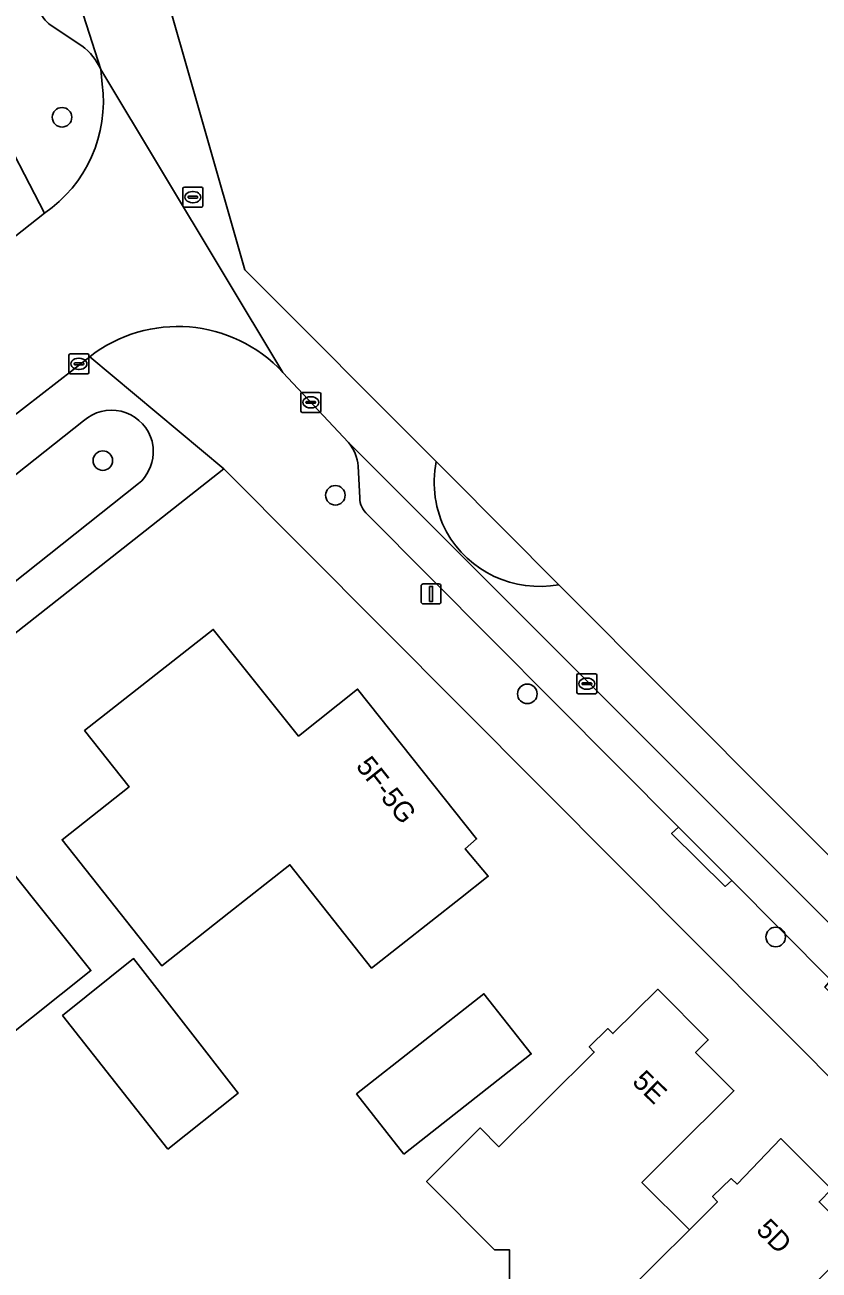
# Model space of a CAD drawing. Extents: x 159499 to 160349, y 382524 to 383273.
# Drawn here: x 160006.4 to 160046.1, y 383112.7 to 383174.9 of the extents above; entities that cross this region are included whole.
import ezdxf

# ---------------------------------------------------------------- set-up
doc = ezdxf.new("R2010")
doc.units = 0
for name, color, linetype in [('IMGEO_Boom', 7, 'Continuous'), ('IMGEO_Erf', 7, 'Continuous'), ('IMGEO_Groenvoorziening', 7, 'Continuous'), ('IMGEO_Kolk', 7, 'Continuous'), ('IMGEO_Lichtmast', 7, 'Continuous'), ('IMGEO_Pand', 7, 'Continuous'), ('IMGEO_Pand_nummerreeks', 7, 'Continuous'), ('IMGEO_Parkeervlak_open', 7, 'Continuous'), ('IMGEO_Rijbaan_lokaal_open', 7, 'Continuous'), ('IMGEO_Rioolput', 7, 'Continuous'), ('IMGEO_Voetpad_open', 7, 'Continuous')]:
    doc.layers.add(name, color=color, linetype=linetype)

msp = doc.modelspace()

# ---------------------------------------------------------------- linework, layer by layer
at = {"layer": 'IMGEO_Boom'}
for centre in [(160008.214, 383170.317), (160010.256, 383153.147), (160021.884, 383151.415), (160031.484, 383141.482), (160043.906, 383129.323)]:
    msp.add_circle(centre, 0.489, dxfattribs=at)
at = {"layer": 'IMGEO_Erf'}
for points in [[(160069.07, 383073.156), (160071.919, 383076.914), (160077.006, 383081.993), (160081.991, 383086.829), (160067.75, 383101.08), (160016.301, 383152.744), (160001.274, 383140.9), (160002.826, 383138.938), (160000, 383136.696), (159969.339, 383112.369), (160000, 383073.962), (160006.879, 383065.344), (160051.214, 383033.728), (160053.92, 383031.798), (160060.452, 383040.944)], [(160030.58, 383110.504), (160030.598, 383113.675), (160029.836, 383113.679), (160026.442, 383117.102), (160029.132, 383119.771), (160030.062, 383118.834), (160034.833, 383123.565), (160034.577, 383123.828), (160035.504, 383124.744), (160035.763, 383124.493), (160038.003, 383126.714), (160040.531, 383124.177), (160039.901, 383123.546), (160041.817, 383121.634), (160038.641, 383118.472), (160037.215, 383117.052), (160039.586, 383114.674), (160040.99, 383116.079), (160040.749, 383116.34), (160041.669, 383117.242), (160041.984, 383116.966), (160044.168, 383119.245), (160046.692, 383116.707)]]:
    msp.add_lwpolyline(points, dxfattribs=at)
for points in [[(160016.558, 383130.525), (160013.211, 383127.876), (160008.217, 383134.186), (160011.565, 383136.836), (160009.341, 383139.648), (160015.779, 383144.707), (160020.043, 383139.37), (160022.992, 383141.72), (160028.948, 383134.232), (160028.37, 383133.728), (160029.529, 383132.362), (160028.136, 383131.264), (160023.699, 383127.767), (160019.608, 383132.939)], [(160004.209, 383119.058), (160002.296, 383117.538), (160002.349, 383117.471), (160000, 383115.631), (159996.451, 383112.851), (159994.2, 383115.629), (159990.696, 383112.874), (159987.999, 383116.264), (159984.887, 383120.176), (159990.894, 383124.991), (159992.99, 383122.344), (159994.232, 383120.776), (159997.365, 383123.295), (159996.151, 383124.828), (159996.416, 383125.034), (159998.829, 383121.957), (160000.398, 383123.188), (160000, 383123.688), (159995.843, 383128.911), (160000, 383132.215), (160003.671, 383135.132), (160006.794, 383131.227), (160009.659, 383127.643), (160002.137, 383121.666)], [(160013.507, 383118.714), (160008.245, 383125.389), (160011.792, 383128.245), (160017.019, 383121.506)], [(160025.306, 383118.47), (160022.943, 383121.478), (160029.314, 383126.485), (160031.676, 383123.476)]]:
    msp.add_lwpolyline(points, close=True, dxfattribs=at)
at = {"layer": 'IMGEO_Groenvoorziening'}
for points in [[(160009.287, 383155.131), (160000, 383147.78), (159987.796, 383138.118), (159990.398, 383134.835), (160000, 383142.448), (160012.044, 383151.997)], [(160012.775, 383153.48), (160012.772, 383153.8), (160012.72, 383154.114), (160012.639, 383154.337)]]:
    msp.add_lwpolyline(points, dxfattribs=at)
for centre, radius, start, end in [((160010.691, 383153.585), 2.088, 21.1107, 132.23683), ((160010.695, 383153.584), 2.083, 310.37848, 357.14233)]:
    msp.add_arc(centre, radius, start, end, dxfattribs=at)
at = {"layer": 'IMGEO_Kolk'}
for p, q in [((160008.56, 383157.561), (160008.56, 383158.413)), ((160008.635, 383158.487), (160009.487, 383158.487)), ((160008.819, 383157.981), (160008.819, 383157.993)), ((160009.257, 383157.944), (160008.859, 383157.944)), ((160008.862, 383158.03), (160009.26, 383158.03)), ((160009.048, 383158.267), (160009.073, 383158.267)), ((160009.303, 383157.993), (160009.303, 383157.981)), ((160009.561, 383158.413), (160009.561, 383157.561)), ((160009.487, 383157.487), (160008.635, 383157.487)), ((160009.071, 383157.707), (160009.046, 383157.707)), ((160020.154, 383155.635), (160020.154, 383156.487)), ((160020.229, 383156.561), (160021.081, 383156.561)), ((160020.413, 383156.055), (160020.413, 383156.067)), ((160020.456, 383156.104), (160020.854, 383156.104)), ((160020.642, 383156.341), (160020.667, 383156.341)), ((160020.897, 383156.067), (160020.897, 383156.055)), ((160021.155, 383156.487), (160021.155, 383155.635)), ((160021.081, 383155.561), (160020.229, 383155.561)), ((160020.851, 383156.018), (160020.453, 383156.018)), ((160020.665, 383155.781), (160020.64, 383155.781)), ((160033.959, 383141.564), (160033.959, 383142.416)), ((160034.034, 383142.49), (160034.886, 383142.49)), ((160034.96, 383142.416), (160034.96, 383141.564)), ((160034.218, 383141.984), (160034.218, 383141.996)), ((160034.656, 383141.947), (160034.258, 383141.947)), ((160034.261, 383142.033), (160034.659, 383142.033)), ((160034.447, 383142.27), (160034.472, 383142.27)), ((160034.702, 383141.996), (160034.702, 383141.984)), ((160034.886, 383141.49), (160034.034, 383141.49)), ((160034.47, 383141.71), (160034.445, 383141.71))]:
    msp.add_line(p, q, dxfattribs=at)
for points in [[(160008.56, 383157.561), (160008.56, 383158.413)], [(160008.635, 383158.487), (160009.487, 383158.487)], [(160009.561, 383158.413), (160009.561, 383157.561)], [(160009.487, 383157.487), (160008.635, 383157.487)], [(160020.154, 383155.635), (160020.154, 383156.487)], [(160020.229, 383156.561), (160021.081, 383156.561)], [(160021.155, 383156.487), (160021.155, 383155.635)], [(160021.081, 383155.561), (160020.229, 383155.561)], [(160033.959, 383141.564), (160033.959, 383142.416)], [(160034.034, 383142.49), (160034.886, 383142.49)], [(160034.96, 383142.416), (160034.96, 383141.564)], [(160034.886, 383141.49), (160034.034, 383141.49)]]:
    msp.add_lwpolyline(points, dxfattribs=at)
for centre, radius, start, end in [((160008.637, 383158.411), 0.0765, 91.55205, 178.44795), ((160008.637, 383158.411), 0.0765, 91.55205, 178.44795), ((160008.859, 383157.99), 0.0403, 85.87752, 175.75265), ((160008.856, 383157.98), 0.0366, 178.93798, 274.71019), ((160009.26, 383157.987), 0.043, 264.86636, 352.45326), ((160009.264, 383157.992), 0.0386, 1.73085, 96.63898), ((160009.485, 383158.411), 0.0765, 1.55205, 88.44795), ((160009.485, 383158.411), 0.0765, 1.55205, 88.44795), ((160008.637, 383157.563), 0.0765, 181.55205, 268.44795), ((160008.637, 383157.563), 0.0765, 181.55205, 268.44795), ((160009.485, 383157.563), 0.0765, 271.55205, 358.44795), ((160009.485, 383157.563), 0.0765, 271.55205, 358.44795), ((160020.231, 383156.485), 0.0765, 91.55205, 178.44795), ((160020.231, 383156.485), 0.0765, 91.55205, 178.44795), ((160020.453, 383156.064), 0.0403, 85.87752, 175.75265), ((160020.45, 383156.054), 0.0366, 178.93798, 274.71019), ((160020.854, 383156.061), 0.043, 264.86636, 352.45326), ((160020.858, 383156.066), 0.0386, 1.73085, 96.63898), ((160021.079, 383156.485), 0.0765, 1.55205, 88.44795), ((160021.079, 383156.485), 0.0765, 1.55205, 88.44795), ((160020.231, 383155.637), 0.0765, 181.55205, 268.44795), ((160020.231, 383155.637), 0.0765, 181.55205, 268.44795), ((160021.079, 383155.637), 0.0765, 271.55205, 358.44795), ((160021.079, 383155.637), 0.0765, 271.55205, 358.44795), ((160034.036, 383142.414), 0.0765, 91.55205, 178.44795), ((160034.036, 383142.414), 0.0765, 91.55205, 178.44795), ((160034.884, 383142.414), 0.0765, 1.55205, 88.44795), ((160034.884, 383142.414), 0.0765, 1.55205, 88.44795), ((160034.258, 383141.993), 0.0403, 85.87752, 175.75265), ((160034.255, 383141.983), 0.0366, 178.93798, 274.71019), ((160034.659, 383141.99), 0.043, 264.86636, 352.45326), ((160034.663, 383141.995), 0.0386, 1.73085, 96.63898), ((160034.036, 383141.566), 0.0765, 181.55205, 268.44795), ((160034.036, 383141.566), 0.0765, 181.55205, 268.44795), ((160034.884, 383141.566), 0.0765, 271.55205, 358.44795), ((160034.884, 383141.566), 0.0765, 271.55205, 358.44795)]:
    msp.add_arc(centre, radius, start, end, dxfattribs=at)
for centre, major_axis, ratio, start_param, end_param in [((160009.047, 383157.987), (-0.387, 0.002), 0.722429, 4.712389, 7.853982), ((160009.072, 383157.987), (-0.39, 0.002), 0.717154, 1.570796, 4.712389), ((160020.641, 383156.061), (-0.387, 0.002), 0.722429, 4.712389, 7.853982), ((160020.666, 383156.061), (-0.39, 0.002), 0.717154, 1.570796, 4.712389), ((160034.446, 383141.99), (-0.387, 0.002), 0.722429, 4.712389, 7.853982), ((160034.471, 383141.99), (-0.39, 0.002), 0.717154, 1.570796, 4.712389)]:
    msp.add_ellipse(centre, major_axis=major_axis, ratio=ratio, start_param=start_param, end_param=end_param, dxfattribs=at)
at = {"layer": 'IMGEO_Lichtmast'}
for p, q in [((160026.174, 383146.083), (160026.174, 383146.883)), ((160026.174, 383146.883), (160026.174, 383146.083)), ((160026.274, 383146.983), (160027.064, 383146.983)), ((160027.064, 383146.983), (160026.274, 383146.983)), ((160027.164, 383146.883), (160027.164, 383146.083)), ((160027.164, 383146.083), (160027.164, 383146.883)), ((160027.064, 383145.983), (160026.274, 383145.983)), ((160026.274, 383145.983), (160027.064, 383145.983))]:
    msp.add_line(p, q, dxfattribs=at)
msp.add_lwpolyline([(160026.594, 383146.858), (160026.744, 383146.858), (160026.744, 383146.108), (160026.594, 383146.108), (160026.594, 383146.858)], dxfattribs=at)
for centre, start, end in [((160026.274, 383146.883), 90, 180), ((160026.274, 383146.883), 90, 180), ((160027.064, 383146.883), 0, 90), ((160027.064, 383146.883), 360, 90), ((160026.274, 383146.083), 180, 270), ((160026.274, 383146.083), 180, 270), ((160027.064, 383146.083), 270, 0), ((160027.064, 383146.083), 270, 0)]:
    msp.add_arc(centre, 0.1, start, end, dxfattribs=at)
at = {"layer": 'IMGEO_Pand'}
for points in [[(160022.992, 383141.72), (160020.043, 383139.37), (160015.779, 383144.707), (160009.341, 383139.648), (160011.565, 383136.836), (160008.217, 383134.186), (160013.211, 383127.876), (160016.558, 383130.525), (160019.608, 383132.939), (160023.699, 383127.767), (160028.136, 383131.264), (160029.529, 383132.362), (160028.37, 383133.728), (160028.948, 383134.232)], [(160006.794, 383131.227), (160003.671, 383135.132), (160000, 383132.215), (159995.843, 383128.911), (160000, 383123.688), (160000.398, 383123.188), (159998.829, 383121.957), (159999.502, 383121.1), (160000, 383120.466), (160002.296, 383117.538), (160004.209, 383119.058), (160002.137, 383121.666), (160009.659, 383127.643)], [(160013.507, 383118.714), (160017.019, 383121.506), (160011.792, 383128.245), (160008.245, 383125.389)], [(160025.306, 383118.47), (160031.676, 383123.476), (160029.314, 383126.485), (160022.943, 383121.478)], [(160036.311, 383111.257), (160036.228, 383111.34), (160039.586, 383114.674), (160037.215, 383117.052), (160038.641, 383118.472), (160041.817, 383121.634), (160039.901, 383123.546), (160040.531, 383124.177), (160038.003, 383126.714), (160035.763, 383124.493), (160035.504, 383124.744), (160034.577, 383123.828), (160034.833, 383123.565), (160030.062, 383118.834), (160029.132, 383119.771), (160026.442, 383117.102), (160029.836, 383113.679), (160030.598, 383113.675), (160030.58, 383110.504), (160032.964, 383108.099), (160033.044, 383108.018)], [(160047.989, 383114.149), (160046.077, 383116.072), (160046.692, 383116.707), (160044.168, 383119.245), (160041.984, 383116.966), (160041.669, 383117.242), (160040.749, 383116.34), (160040.99, 383116.079), (160039.586, 383114.674), (160036.228, 383111.34), (160036.311, 383111.257), (160038.846, 383108.701), (160036.851, 383106.723), (160036.843, 383102.926), (160039.147, 383100.602), (160042.399, 383103.856), (160045.76, 383107.219), (160043.439, 383109.554)]]:
    msp.add_lwpolyline(points, close=True, dxfattribs=at)
at = {"layer": 'IMGEO_Parkeervlak_open'}
for points in [[(160010.148, 383172.703), (160009.286, 383175.416), (160008.427, 383178.634), (160001.127, 383207.052)], [(160007.624, 383174.938), (160009.21, 383173.884)], [(160076.557, 383100.013), (160076.086, 383100.485), (160022.535, 383154.053)], [(160023.019, 383152.872), (160023.102, 383151.29)], [(160023.491, 383150.457), (160039.036, 383134.817), (160041.708, 383132.149), (160046.658, 383127.167), (160049.325, 383124.473), (160053.562, 383120.199), (160056.249, 383117.477), (160059.79, 383113.973), (160066.209, 383107.501), (160070.134, 383103.56), (160072.795, 383100.861)]]:
    msp.add_lwpolyline(points, dxfattribs=at)
for centre, radius, start, end in [((160008.417, 383176.075), 1.386, 197.12192, 235.11954), ((160007.643, 383171.676), 2.707, 22.28585, 54.63032), ((160020.952, 383152.714), 2.073, 4.35881, 40.211), ((160024.232, 383151.31), 1.13, 181.02247, 229.04143)]:
    msp.add_arc(centre, radius, start, end, dxfattribs=at)
at = {"layer": 'IMGEO_Rijbaan_lokaal_open'}
for points in [[(160026.926, 383153.096), (160017.356, 383162.697), (160004.31, 383208.29), (160003.465, 383211.242), (159997.514, 383226.3), (159968.231, 383262.808), (159963.898, 383259.136), (159970.978, 383250.787), (159972.768, 383248.666), (159984.285, 383235.173), (159987.671, 383231.155), (159988.81, 383229.825), (159991.015, 383227.22), (159992.828, 383224.63), (159995.219, 383220.768), (159995.36, 383220.508), (159997.004, 383217.494)], [(160001.127, 383207.052), (160008.427, 383178.634), (160009.286, 383175.416), (160010.148, 383172.703), (160019.26, 383157.562), (160022.535, 383154.053), (160076.086, 383100.485), (160077.721, 383102.136)], [(160019.26, 383157.562), (160010.148, 383172.703), (160010.226, 383171.982)], [(160007.337, 383165.518), (159985.41, 383148.209), (159982.548, 383145.937), (159982.197, 383145.658), (159979.79, 383143.748), (159968.366, 383134.687), (159965.633, 383132.52), (159965.323, 383132.274), (159962.64, 383130.146), (159961.424, 383129.181), (159965.635, 383123.738), (160005.521, 383155.177), (160009.599, 383158.345)], [(160033.061, 383146.941), (160027.541, 383152.479), (160026.926, 383153.096)], [(160077.721, 383102.136), (160033.061, 383146.941)]]:
    msp.add_lwpolyline(points, dxfattribs=at)
for centre, radius, start, end in [((160003.506, 383171.108), 6.776, 304.42366, 7.41309), ((160014.002, 383152.682), 7.173, 42.86559, 127.8673), ((160032.169, 383152.066), 5.343, 168.88651, 207.71092), ((160032.169, 383152.066), 5.343, 168.88651, 207.71092), ((160032.093, 383152.187), 5.334, 209.24423, 280.45081), ((160032.093, 383152.187), 5.334, 209.24423, 280.45081)]:
    msp.add_arc(centre, radius, start, end, dxfattribs=at)
at = {"layer": 'IMGEO_Rioolput'}
for p, q in [((160014.257, 383165.898), (160014.257, 383166.75)), ((160014.332, 383166.824), (160015.184, 383166.824)), ((160015.258, 383166.75), (160015.258, 383165.898)), ((160014.516, 383166.318), (160014.516, 383166.33)), ((160014.954, 383166.281), (160014.556, 383166.281)), ((160014.559, 383166.367), (160014.957, 383166.367)), ((160014.768, 383166.044), (160014.743, 383166.044)), ((160014.745, 383166.604), (160014.77, 383166.604)), ((160015, 383166.33), (160015, 383166.318)), ((160015.184, 383165.824), (160014.332, 383165.824))]:
    msp.add_line(p, q, dxfattribs=at)
for points in [[(160014.257, 383165.898), (160014.257, 383166.75)], [(160014.332, 383166.824), (160015.184, 383166.824)], [(160015.258, 383166.75), (160015.258, 383165.898)], [(160015.184, 383165.824), (160014.332, 383165.824)]]:
    msp.add_lwpolyline(points, dxfattribs=at)
for centre, radius, start, end in [((160014.334, 383166.748), 0.0765, 91.55205, 178.44795), ((160014.334, 383166.748), 0.0765, 91.55205, 178.44795), ((160015.182, 383166.748), 0.0765, 1.55205, 88.44795), ((160015.182, 383166.748), 0.0765, 1.55205, 88.44795), ((160014.556, 383166.327), 0.0403, 85.87752, 175.75265), ((160014.553, 383166.317), 0.0366, 178.93798, 274.71019), ((160014.957, 383166.324), 0.043, 264.86636, 352.45326), ((160014.961, 383166.329), 0.0386, 1.73085, 96.63898), ((160014.334, 383165.9), 0.0765, 181.55205, 268.44795), ((160014.334, 383165.9), 0.0765, 181.55205, 268.44795), ((160015.182, 383165.9), 0.0765, 271.55205, 358.44795), ((160015.182, 383165.9), 0.0765, 271.55205, 358.44795)]:
    msp.add_arc(centre, radius, start, end, dxfattribs=at)
for centre, major_axis, ratio, start_param, end_param in [((160014.744, 383166.324), (-0.387, 0.002), 0.722429, 4.712389, 7.853982), ((160014.769, 383166.324), (-0.39, 0.002), 0.717154, 1.570796, 4.712389)]:
    msp.add_ellipse(centre, major_axis=major_axis, ratio=ratio, start_param=start_param, end_param=end_param, dxfattribs=at)
at = {"layer": 'IMGEO_Voetpad_open'}
for points in [[(160004.185, 383187.101), (160003.787, 383187.001), (160001.503, 383195.72), (160001.965, 383195.837), (159998.943, 383207.485), (159995.626, 383206.655), (159998.754, 383194.224), (160000, 383189.273), (160000.67, 383186.646), (160004.812, 383170.397), (160007.337, 383165.518)], [(160009.21, 383173.884), (160007.624, 383174.938)], [(160010.226, 383171.982), (160010.148, 383172.703)], [(159985.41, 383148.209), (160007.337, 383165.518), (160004.812, 383170.397)], [(160012.044, 383151.997), (160000, 383142.448), (160001.274, 383140.9), (160016.301, 383152.744), (160009.599, 383158.345), (160005.521, 383155.177)], [(160009.599, 383158.345), (160016.301, 383152.744), (160067.75, 383101.08), (160081.991, 383086.829), (160083.322, 383085.497), (160085.634, 383087.791)], [(160022.535, 383154.053), (160019.26, 383157.562)], [(159986.191, 383136.82), (159988.759, 383133.521), (159990.398, 383134.835), (159987.796, 383138.118), (160000, 383147.78), (160009.287, 383155.131)], [(160012.639, 383154.337), (160012.72, 383154.114), (160012.772, 383153.8), (160012.775, 383153.48)], [(160023.102, 383151.29), (160023.019, 383152.872)], [(160041.708, 383132.149), (160041.384, 383131.851), (160038.699, 383134.501), (160039.036, 383134.817), (160023.491, 383150.457)], [(160072.795, 383100.861), (160072.502, 383100.579), (160069.86, 383103.237), (160070.134, 383103.56), (160066.209, 383107.501), (160065.937, 383107.22), (160059.481, 383113.631), (160059.79, 383113.973), (160056.249, 383117.477), (160055.95, 383117.225), (160053.254, 383119.875), (160053.562, 383120.199), (160049.325, 383124.473), (160048.986, 383124.177), (160046.357, 383126.82), (160046.658, 383127.167), (160041.708, 383132.149)]]:
    msp.add_lwpolyline(points, dxfattribs=at)
msp.add_lwpolyline([(160041.708, 383132.149), (160039.036, 383134.817), (160038.699, 383134.501), (160041.384, 383131.851)], close=True, dxfattribs=at)
for centre, radius, start, end in [((160008.417, 383176.075), 1.386, 197.12192, 235.11954), ((160007.643, 383171.676), 2.707, 22.28585, 54.63032), ((160003.506, 383171.108), 6.776, 304.42366, 7.41309), ((160014.002, 383152.682), 7.173, 42.86559, 127.8673), ((160010.691, 383153.585), 2.088, 21.1107, 132.23683), ((160020.952, 383152.714), 2.073, 4.35881, 40.211), ((160010.695, 383153.584), 2.083, 310.37848, 357.14233), ((160024.232, 383151.31), 1.13, 181.02247, 229.04143)]:
    msp.add_arc(centre, radius, start, end, dxfattribs=at)

# ---------------------------------------------------------------- texts
at = {"layer": 'IMGEO_Pand_nummerreeks'}
for s, rotation, p in [('5F-5G', 308.49682, (160022.872, 383137.855)), ('5E', 316.05431, (160036.679, 383122.03)), ('5D', 315.04573, (160042.878, 383114.617))]:
    msp.add_text(s, height=1, rotation=rotation, dxfattribs=at).set_placement(p)

doc.saveas('drawing.dxf')
